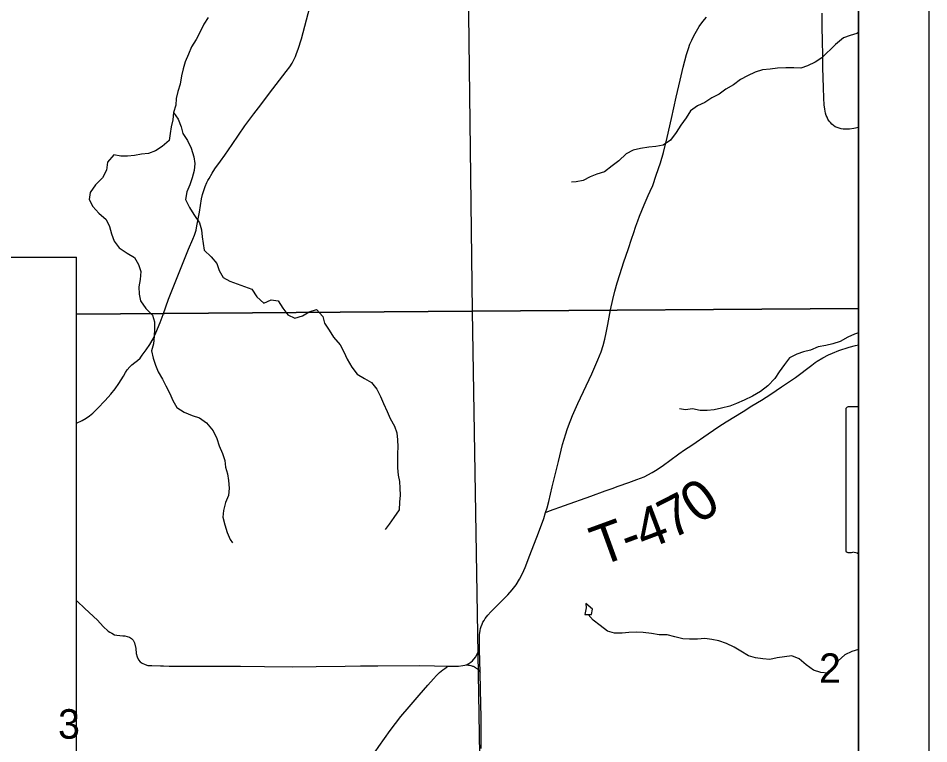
# Model space of a CAD drawing. Extents: x 0 to 34, y 0 to 22.
# Drawn here: x 7.465 to 8.76, y 16.159 to 17.19 of the extents above; entities that cross this region are included whole.
import ezdxf

# ---------------------------------------------------------------- set-up
doc = ezdxf.new("R2010")
doc.units = 0
for name, color, linetype in [('GM_X_County_Road', 7, 'Continuous'), ('GM_X_County_Road_Text', 7, 'Continuous'), ('GM_X_Interchange_Ramps', 7, 'Continuous'), ('GM_X_Minor_River_Text', 7, 'Continuous'), ('GM_X_State_Location', 7, 'Continuous'), ('GM_X_State_Route', 7, 'Continuous'), ('GM_X_Township_Text', 7, 'Continuous'), ('GM_X_Unincorporated_Location', 7, 'Continuous'), ('SH_Data', 7, 'Continuous'), ('SH_Text', 7, 'Continuous')]:
    doc.layers.add(name, color=color, linetype=linetype)

msp = doc.modelspace()

# ---------------------------------------------------------------- linework, layer by layer
at = {"layer": 'GM_X_County_Road'}
msp.add_lwpolyline([(8.6602, 17.0346), (8.6537, 17.0334), (8.6477, 17.0325), (8.6416, 17.0323), (8.6386, 17.0325), (8.6356, 17.0329), (8.6327, 17.0337), (8.6299, 17.0347), (8.6272, 17.036), (8.6247, 17.0376), (8.6224, 17.0395), (8.6203, 17.0417), (8.6184, 17.044), (8.6168, 17.0466), (8.6155, 17.0493), (8.6144, 17.0521), (8.6135, 17.055), (8.6122, 17.061), (8.6115, 17.0671), (8.6111, 17.0764), (8.6106, 17.0918), (8.6097, 17.1197), (8.6094, 17.1353), (8.6091, 17.1601), (8.6088, 17.1756), (8.6085, 17.1973)], dxfattribs=at)
at = {"layer": 'GM_X_County_Road_Text'}
for points in [[(7.7354, 17.1914), (7.7293, 17.1816), (7.7242, 17.171), (7.7185, 17.1601), (7.7116, 17.1495), (7.7077, 17.1389), (7.703, 17.128), (7.6999, 17.1181), (7.6976, 17.1083), (7.6959, 17.0962), (7.6925, 17.086), (7.6901, 17.0761), (7.6893, 17.0667), (7.6861, 17.0561), (7.6853, 17.0458), (7.6829, 17.036), (7.6813, 17.0261), (7.6801, 17.0163), (7.6702, 17.0077), (7.6607, 17.0017), (7.6504, 16.998), (7.6405, 16.9969), (7.6307, 16.9951), (7.6208, 16.9941), (7.6113, 16.9942), (7.6015, 16.9962), (7.5923, 16.9856), (7.5907, 16.9743), (7.5853, 16.9633), (7.5754, 16.9532), (7.5677, 16.9426), (7.5661, 16.9324), (7.5713, 16.9225), (7.58, 16.9129), (7.5905, 16.9041), (7.5953, 16.8942), (7.5979, 16.8836), (7.602, 16.8733), (7.6087, 16.8637), (7.6201, 16.8564), (7.6306, 16.8499), (7.6362, 16.84), (7.6395, 16.8301), (7.6387, 16.8187), (7.6371, 16.8081), (7.6374, 16.7979), (7.6392, 16.7884), (7.6467, 16.7777), (7.6565, 16.7681), (7.6594, 16.7586), (7.6593, 16.7484), (7.6585, 16.7381), (7.6576, 16.7272), (7.6549, 16.7173), (7.6575, 16.7071), (7.6608, 16.6972), (7.6645, 16.6873), (7.6705, 16.677), (7.6753, 16.6675), (7.6809, 16.6568), (7.6854, 16.6469), (7.691, 16.6366), (7.7012, 16.6301), (7.7125, 16.6254), (7.7231, 16.6219), (7.7329, 16.615), (7.7427, 16.6035), (7.7479, 16.5929), (7.7512, 16.5822), (7.756, 16.5715), (7.759, 16.5613), (7.76, 16.5518), (7.763, 16.5423), (7.7644, 16.5328)], [(8.6602, 17.17), (8.6578, 17.1683), (8.6483, 17.1657), (8.6388, 17.1624), (8.6277, 17.153), (8.6082, 17.1338), (8.5987, 17.1275), (8.5876, 17.1226), (8.5781, 17.1193), (8.5683, 17.1198), (8.5569, 17.1195), (8.5452, 17.1192), (8.5349, 17.1178), (8.5239, 17.1168), (8.5133, 17.1134), (8.5026, 17.1082), (8.4923, 17.103), (8.4824, 17.0955), (8.4718, 17.0892), (8.4622, 17.082), (8.4516, 17.0772), (8.4417, 17.0705), (8.4314, 17.0656), (8.4215, 17.0585), (8.4153, 17.0487), (8.4077, 17.0382), (8.4011, 17.0276), (8.3931, 17.0167), (8.3824, 17.0096), (8.3722, 17.0078), (8.3619, 17.0071), (8.3505, 17.0049), (8.3399, 17.0024), (8.33, 16.9972), (8.3197, 16.9874), (8.3101, 16.9803), (8.2991, 16.9716), (8.2884, 16.9683), (8.2786, 16.9646), (8.2687, 16.9594), (8.2588, 16.9576), (8.252, 16.9569)], [(7.6861, 17.0561), (7.6929, 17.0465), (7.697, 17.0359), (7.6995, 17.0264), (7.7059, 17.0164), (7.7115, 17.0054), (7.7152, 16.9932), (7.7166, 16.9837), (7.7158, 16.9735), (7.7127, 16.9633), (7.7092, 16.9535), (7.7053, 16.9433), (7.7033, 16.9323), (7.7089, 16.9212), (7.7153, 16.9113), (7.7231, 16.8991), (7.7261, 16.8892), (7.7271, 16.8794), (7.7286, 16.8699), (7.7296, 16.8604), (7.7398, 16.8512), (7.7477, 16.8416), (7.751, 16.8317), (7.7566, 16.8218), (7.7664, 16.8164), (7.7766, 16.8125), (7.7872, 16.809), (7.7974, 16.8052), (7.8049, 16.7941), (7.8147, 16.7849), (7.8249, 16.7897), (7.8348, 16.7885), (7.8419, 16.7782), (7.849, 16.7687), (7.8588, 16.7636), (7.8695, 16.7673), (7.879, 16.7726), (7.8896, 16.7763), (7.8986, 16.7663), (7.9008, 16.7568), (7.9076, 16.7469), (7.9139, 16.7366), (7.9233, 16.7259), (7.9282, 16.716), (7.933, 16.7057), (7.9397, 16.6939), (7.9472, 16.6843), (7.9578, 16.6778), (7.9676, 16.6724), (7.9755, 16.6629), (7.9807, 16.6522), (7.9848, 16.6427), (7.99, 16.6312), (7.9945, 16.6213), (8.0004, 16.6103), (8.0038, 16.6008), (8.0048, 16.5909), (8.0051, 16.5811), (8.0047, 16.5716), (8.0046, 16.5613), (8.0049, 16.5511), (8.0059, 16.5408), (8.0074, 16.5314), (8.0081, 16.5219), (8.0084, 16.512), (8.0075, 16.5022), (8.007, 16.4912), (7.9994, 16.4806), (7.9928, 16.4708), (7.9871, 16.4633)], [(8.6602, 16.7428), (8.6546, 16.7409), (8.6451, 16.7368), (8.634, 16.7308), (8.6238, 16.7272), (8.6139, 16.725), (8.6029, 16.7228), (8.5922, 16.7183), (8.582, 16.7158), (8.5725, 16.7124), (8.5622, 16.7076), (8.5549, 16.6978), (8.5476, 16.6876), (8.5411, 16.6778), (8.5312, 16.6677), (8.5209, 16.6594), (8.5095, 16.6527), (8.4977, 16.6471), (8.487, 16.6423), (8.4775, 16.6386), (8.4657, 16.6357), (8.4551, 16.6335), (8.4449, 16.6324), (8.435, 16.6325), (8.424, 16.6349), (8.4142, 16.6335), (8.4058, 16.6347)], [(7.7644, 16.5328), (7.7655, 16.5222), (7.7646, 16.5119), (7.76, 16.5017), (7.7573, 16.4904), (7.7564, 16.4809), (7.7594, 16.4699), (7.7627, 16.4592), (7.7668, 16.4493), (7.7701, 16.4444)], [(8.6602, 16.293), (8.6509, 16.2897), (8.641, 16.2852), (8.6314, 16.2766), (8.6264, 16.2668), (8.6169, 16.2593), (8.6066, 16.2601), (8.5964, 16.2632), (8.5859, 16.2709), (8.5761, 16.2793), (8.5655, 16.2836), (8.5549, 16.2822), (8.5447, 16.2808), (8.534, 16.2786), (8.5242, 16.2794), (8.514, 16.281), (8.5041, 16.2838), (8.4932, 16.2903), (8.4834, 16.2961), (8.4728, 16.3015), (8.4618, 16.305), (8.4516, 16.307), (8.4418, 16.3082), (8.4315, 16.3076), (8.4202, 16.3073), (8.4103, 16.3081), (8.399, 16.3109), (8.3884, 16.3137), (8.3766, 16.3138), (8.3657, 16.3154), (8.3543, 16.317), (8.3445, 16.3175), (8.3338, 16.3168), (8.3243, 16.3158), (8.3134, 16.3159), (8.3035, 16.319), (8.293, 16.327), (8.2832, 16.3343), (8.2759, 16.3424)]]:
    msp.add_lwpolyline(points, dxfattribs=at)
at = {"layer": 'GM_X_Interchange_Ramps'}
msp.add_line((8.1221, 16.2599), (8.1212, 16.293), dxfattribs=at)
for points in [[(7.5483, 16.6143), (7.5564, 16.6183), (7.5618, 16.6214), (7.5669, 16.6249), (7.5716, 16.6288), (7.5783, 16.6353), (7.5889, 16.6466), (7.5973, 16.6558), (7.6031, 16.6631), (7.6085, 16.6707), (7.615, 16.6812), (7.6179, 16.6866), (7.6205, 16.6905), (7.6241, 16.6947), (7.6268, 16.6974), (7.6314, 16.7009), (7.6352, 16.7038), (7.6386, 16.7071), (7.6418, 16.7112), (7.6475, 16.7186), (7.6525, 16.7265), (7.6571, 16.7346), (7.6611, 16.743), (7.6671, 16.7574), (7.6715, 16.769), (7.6789, 16.7909), (7.6894, 16.8168), (7.6997, 16.8431), (7.7073, 16.8619), (7.7138, 16.8759), (7.7161, 16.8819), (7.7184, 16.8891), (7.7196, 16.8948), (7.7231, 16.9146), (7.7262, 16.9334), (7.7275, 16.9394), (7.7292, 16.9453), (7.7312, 16.9511), (7.7338, 16.9567), (7.7352, 16.9594), (7.7368, 16.9625), (7.7411, 16.9697), (7.7451, 16.9761), (7.753, 16.9871), (7.759, 16.9955), (7.7697, 17.0107), (7.7784, 17.0241), (7.7874, 17.0373), (7.8003, 17.0544), (7.8104, 17.067), (7.8225, 17.0837), (7.8463, 17.1143), (7.8514, 17.1212), (7.8547, 17.1264), (7.8572, 17.1308), (7.8597, 17.1358), (7.8613, 17.1402), (7.8636, 17.1463), (7.868, 17.161), (7.8754, 17.188), (7.8799, 17.2061)], [(8.2154, 16.4877), (8.2174, 16.494), (8.2198, 16.503), (8.2249, 16.524), (8.2335, 16.5602), (8.2396, 16.5843), (8.244, 16.5992), (8.2461, 16.6055), (8.2481, 16.6109), (8.2538, 16.6253), (8.2613, 16.6424), (8.281, 16.6846), (8.2898, 16.7045), (8.2943, 16.716), (8.2971, 16.7249), (8.2995, 16.7338), (8.3015, 16.7428), (8.3038, 16.7548), (8.3077, 16.7756), (8.3109, 16.7904), (8.3138, 16.8023), (8.317, 16.8142), (8.3207, 16.826), (8.3265, 16.8437), (8.3327, 16.8613), (8.3378, 16.8773), (8.3401, 16.8841), (8.3436, 16.8947), (8.3463, 16.9021), (8.3487, 16.9086), (8.3556, 16.9249), (8.3614, 16.9381), (8.364, 16.9442), (8.3676, 16.9523), (8.3728, 16.9669), (8.3785, 16.9846), (8.3829, 16.9995), (8.3884, 17.0205), (8.3945, 17.0478), (8.4012, 17.0781), (8.4066, 17.1023), (8.411, 17.1204), (8.4159, 17.1384), (8.4186, 17.1472), (8.4206, 17.1532), (8.4231, 17.1592), (8.4259, 17.165), (8.4297, 17.1718), (8.4335, 17.1783), (8.4387, 17.1853), (8.444, 17.1918)], [(8.2154, 16.4877), (8.221, 16.4897), (8.242, 16.4974), (8.2798, 16.5109), (8.3001, 16.5185), (8.3099, 16.5218), (8.3185, 16.5248), (8.3337, 16.5303), (8.3452, 16.5344), (8.3555, 16.5383), (8.3669, 16.5442), (8.3741, 16.5488), (8.3828, 16.555), (8.3921, 16.5616), (8.4047, 16.5709), (8.4129, 16.5765), (8.4232, 16.5834), (8.4463, 16.5995), (8.4619, 16.6096), (8.467, 16.613), (8.4723, 16.6162), (8.4964, 16.6309), (8.5087, 16.639), (8.5224, 16.6472), (8.5355, 16.6557), (8.5507, 16.6661), (8.5706, 16.6794), (8.5941, 16.6968), (8.5987, 16.7006), (8.6014, 16.7026), (8.6094, 16.7073), (8.6177, 16.7116), (8.6234, 16.7141), (8.6321, 16.7176), (8.6469, 16.7225), (8.6559, 16.7249), (8.6602, 16.7257)], [(8.1295, 16.3367), (8.1333, 16.3416), (8.1375, 16.3462), (8.1506, 16.3594), (8.1615, 16.3704), (8.1677, 16.3774), (8.1733, 16.3848), (8.1783, 16.3927), (8.1826, 16.401), (8.1863, 16.4095), (8.1931, 16.4269), (8.2053, 16.4588), (8.2127, 16.4792), (8.2154, 16.4877)], [(7.5483, 16.3621), (7.549, 16.3614), (7.5602, 16.351), (7.5782, 16.3346), (7.5864, 16.3255), (7.5932, 16.319), (7.5956, 16.3173), (7.5984, 16.316), (7.6023, 16.3138), (7.6057, 16.313), (7.6143, 16.3122), (7.6172, 16.312), (7.6202, 16.3113), (7.6236, 16.3101), (7.6266, 16.3084), (7.6288, 16.3059), (7.6308, 16.3021), (7.6324, 16.2943), (7.6333, 16.2871), (7.6345, 16.2822), (7.6366, 16.2781), (7.6389, 16.2754), (7.6415, 16.2735), (7.6457, 16.2713), (7.6498, 16.2701), (7.6556, 16.2698), (7.6675, 16.2696), (7.6719, 16.2696), (7.68, 16.2693), (7.6983, 16.2693), (7.7169, 16.2693), (7.7385, 16.2693), (7.7814, 16.2691), (7.8157, 16.2684), (7.8561, 16.2682), (7.889, 16.2684), (7.9303, 16.2691), (7.952, 16.2694), (7.9768, 16.2695), (8.0358, 16.2699), (8.0575, 16.2695), (8.0764, 16.2691)], [(8.1212, 16.293), (8.1211, 16.3042), (8.1214, 16.3136), (8.1222, 16.3197), (8.1229, 16.3227), (8.1238, 16.3257), (8.125, 16.3286), (8.1263, 16.3314), (8.1278, 16.3341), (8.1295, 16.3367)], [(8.1024, 16.271), (8.1036, 16.2714), (8.1063, 16.273), (8.1089, 16.2747), (8.1112, 16.2768), (8.1156, 16.2819), (8.1212, 16.293)], [(7.9251, 16.0776), (7.9328, 16.0886), (7.9449, 16.1065), (7.9554, 16.1218), (7.9678, 16.1396), (7.9783, 16.155), (7.9943, 16.1777), (8.0018, 16.1876), (8.0095, 16.1973), (8.0214, 16.2115), (8.0356, 16.2279), (8.0477, 16.242), (8.0559, 16.2513), (8.0601, 16.2558), (8.0646, 16.26), (8.0694, 16.2639), (8.0719, 16.2657), (8.0764, 16.2691)], [(8.0764, 16.2691), (8.0852, 16.2689), (8.0916, 16.269), (8.0977, 16.2698), (8.1007, 16.2704), (8.1024, 16.271)], [(8.1024, 16.271), (8.1042, 16.2708), (8.1057, 16.2705), (8.1073, 16.2703), (8.1089, 16.27), (8.1103, 16.2696), (8.1114, 16.2693), (8.1125, 16.2689), (8.114, 16.2682), (8.1156, 16.2673), (8.1167, 16.2664), (8.1184, 16.2652), (8.1221, 16.2599)], [(8.1239, 16.1521), (8.1237, 16.1709), (8.1239, 16.1802), (8.1239, 16.1832), (8.1235, 16.1956), (8.1226, 16.236), (8.1221, 16.2599)]]:
    msp.add_lwpolyline(points, dxfattribs=at)
at = {"layer": 'GM_X_Minor_River_Text'}
for points in [[(8.2724, 16.3583), (8.2731, 16.3522), (8.2711, 16.3424), (8.2806, 16.3423)], [(8.2806, 16.3423), (8.2822, 16.3503), (8.2724, 16.3583)]]:
    msp.add_lwpolyline(points, dxfattribs=at)
at = {"layer": 'GM_X_State_Route'}
for points in [[(7.1161, 16.8504), (7.0999, 17.7456), (8.0984, 17.7721), (8.1109, 16.7736), (7.5483, 16.7695)], [(7.5483, 16.7695), (8.1109, 16.7736), (8.1275, 15.7704), (7.1266, 15.779), (7.1265, 15.7834), (7.124, 16.0674)]]:
    msp.add_lwpolyline(points, dxfattribs=at)
for points in [[(8.6602, 16.7776), (8.6602, 17.7718), (8.0984, 17.7721), (8.1109, 16.7736)], [(8.6602, 15.784), (8.6602, 16.7776), (8.1109, 16.7736), (8.1275, 15.7704), (8.3397, 15.7814)]]:
    msp.add_lwpolyline(points, close=True, dxfattribs=at)
at = {"layer": 'GM_X_Unincorporated_Location'}
msp.add_line((8.6423, 16.6341), (8.6423, 16.4341), dxfattribs=at)
msp.add_lwpolyline([(8.6602, 16.4285), (8.6602, 16.6376), (8.6455, 16.6376)], dxfattribs=at)
for centre, major_axis, start_param, end_param in [((8.6461, 16.6346), (0.00382, 0), 1.727492, 3.291633), ((8.6461, 16.4336), (0.00385, 0), 2.993084, 4.5083), ((8.6467, 16.4541), (0.0294, 0), 4.665946, 4.897461), ((8.6527, 16.4225), (0.0106, 0), 0.784316, 1.627899)]:
    msp.add_ellipse(centre, major_axis=major_axis, ratio=0.8, start_param=start_param, end_param=end_param, dxfattribs=at)
at = {"layer": 'SH_Data'}
for points in [[(1.7602, 21.2866), (8.7602, 21.2866), (8.7602, 14.2866), (1.7602, 14.2866)], [(1.8602, 21.1866), (8.6602, 21.1866), (8.6602, 14.3866), (1.8602, 14.3866)]]:
    msp.add_lwpolyline(points, close=True, dxfattribs=at)
at = {"layer": 'SH_Text'}
for p in [(5.4199, 16.8504), (7.5483, 16.0674)]:
    msp.add_line(p, (7.5483, 16.8504), dxfattribs=at)

# ---------------------------------------------------------------- texts
at = {"layer": 'GM_X_State_Location'}
for s, p in [('2', (8.6041, 16.2454)), ('3', (7.522, 16.166))]:
    msp.add_text(s, height=0.0419, rotation=0, dxfattribs=at).set_placement(p)
at = {"layer": 'GM_X_Township_Text'}
for s, rotation, p in [('0', 35.7279, (8.4332, 16.4695)), ('7', 27.1602, (8.3941, 16.4487)), ('4', 20.7393, (8.3551, 16.4334)), ('T', 19.9842, (8.2925, 16.4106)), ('-', 20.114, (8.3325, 16.4252))]:
    msp.add_text(s, height=0.0568, rotation=rotation, dxfattribs=at).set_placement(p)

doc.saveas('drawing.dxf')
